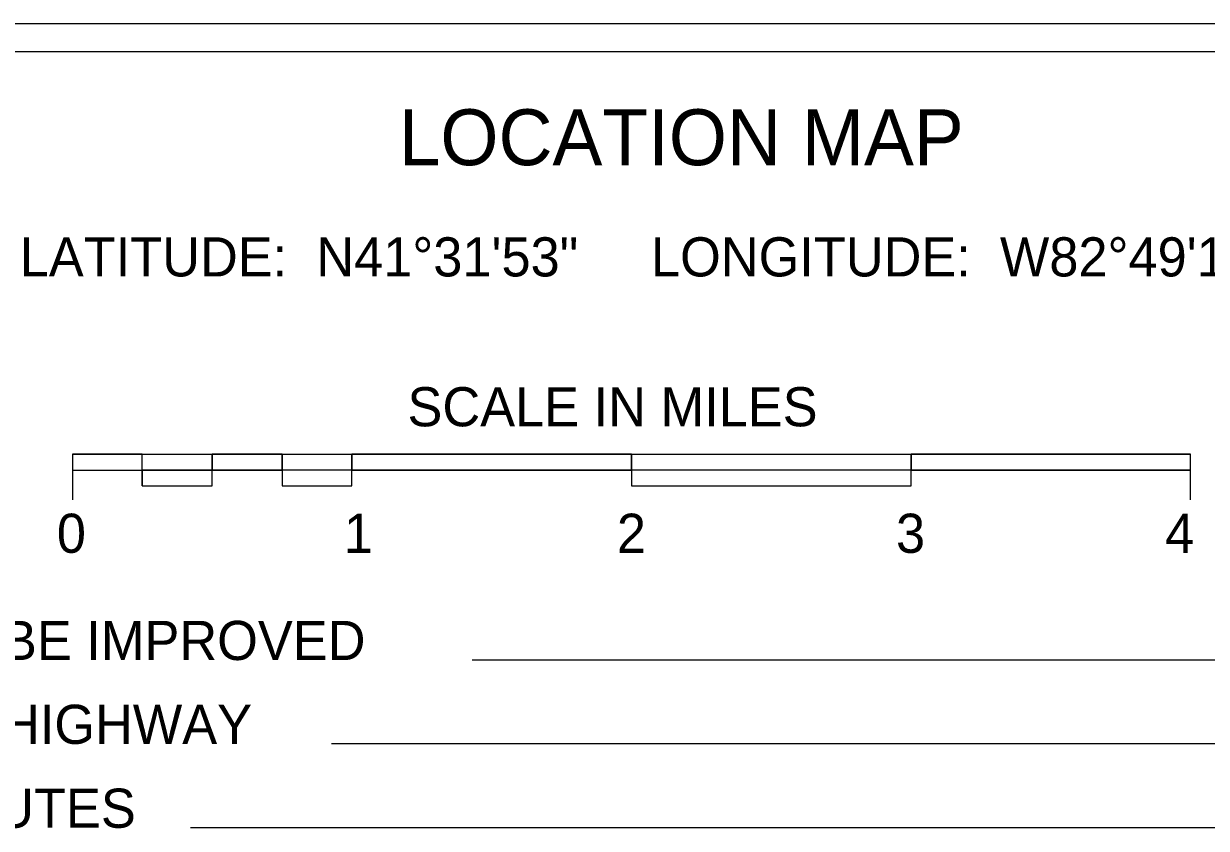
# Model space of a CAD drawing. Extents: x 63.4 to 97.4, y 0.4 to 22.4.
# Drawn here: x 66.497 to 70.728, y 11.642 to 14.52 of the extents above; entities that cross this region are included whole.
import ezdxf

# ---------------------------------------------------------------- set-up
doc = ezdxf.new("R2010")
doc.units = 0
doc.layers.add('SH_Data', color=7, linetype='Continuous')
doc.layers.add('SH_Text', color=7, linetype='Continuous')

msp = doc.modelspace()

# ---------------------------------------------------------------- linework, layer by layer
at = {"layer": 'SH_Data'}
for p, q in [((65.5123, 14.5197), (72.3123, 14.5197)), ((65.4123, 14.4197), (72.4123, 14.4197)), ((66.6718, 12.9796), (66.6718, 12.8171)), ((66.6718, 12.9796), (70.6718, 12.9796)), ((66.9218, 12.8671), (66.9218, 12.9796)), ((67.1718, 12.8671), (67.1718, 12.9796)), ((67.4218, 12.9796), (67.4218, 12.8671)), ((67.6718, 12.8671), (67.6718, 12.9796)), ((68.6718, 12.9796), (68.6718, 12.8671)), ((69.6718, 12.8671), (69.6718, 12.9796)), ((70.6718, 12.8171), (70.6718, 12.9796)), ((66.6718, 12.9233), (66.9218, 12.9233)), ((66.9218, 12.9233), (67.1718, 12.9233)), ((67.1718, 12.9233), (66.9218, 12.9233)), ((66.9218, 12.9233), (66.9218, 12.8671)), ((67.4218, 12.9233), (67.1718, 12.9233)), ((67.1718, 12.8671), (67.1718, 12.9233)), ((67.6718, 12.9233), (67.4218, 12.9233)), ((67.6718, 12.9233), (67.4218, 12.9233)), ((67.4218, 12.9233), (67.4218, 12.8671)), ((68.6718, 12.9233), (67.6718, 12.9233)), ((67.6718, 12.8671), (67.6718, 12.9233)), ((69.6718, 12.9233), (68.6718, 12.9233)), ((69.6718, 12.9233), (68.6718, 12.9233)), ((68.6718, 12.9233), (68.6718, 12.8671)), ((70.6718, 12.9233), (69.6718, 12.9233)), ((69.6718, 12.8671), (69.6718, 12.9233)), ((66.9218, 12.8671), (67.1718, 12.8671)), ((67.4218, 12.8671), (67.6718, 12.8671)), ((68.6718, 12.8671), (69.6718, 12.8671)), ((71.3083, 12.2438), (68.1023, 12.2438)), ((70.9086, 11.9438), (67.5981, 11.9438)), ((70.9086, 11.6438), (67.094, 11.6438))]:
    msp.add_line(p, q, dxfattribs=at)
for points in [[(66.6718, 12.9796), (66.6718, 12.9233), (66.9218, 12.9233), (66.9218, 12.9796)], [(67.1718, 12.9796), (67.1718, 12.9233), (67.4218, 12.9233), (67.4218, 12.9796)], [(67.6718, 12.9796), (67.6718, 12.9233), (68.6718, 12.9233), (68.6718, 12.9796)], [(70.6718, 12.9796), (69.6718, 12.9796), (69.6718, 12.9233), (70.6718, 12.9233)]]:
    msp.add_lwpolyline(points, close=True, dxfattribs=at)

# ---------------------------------------------------------------- texts
for s, p in [('SCALE IN MILES', (67.8704, 13.0796)), ('0', (66.6161, 12.6271)), ('1', (67.6427, 12.6271)), ('2', (68.6194, 12.6271)), ('3', (69.6178, 12.6271)), ('4', (70.5803, 12.6271))]:
    msp.add_text(s, height=0.14, dxfattribs=at).set_placement(p)
at = {"layer": 'SH_Text'}
for s, height, p in [('LOCATION MAP', 0.2, (67.8392, 14.0134)), ('LATITUDE:  N41°31\'53"     LONGITUDE:  W82°49\'19"', 0.14, (66.4833, 13.6156)), ('PORTION TO BE IMPROVED', 0.14, (65.203, 12.2438)), ('INTERSTATE HIGHWAY', 0.14, (65.203, 11.9438)), ('FEDERAL ROUTES', 0.14, (65.203, 11.6438))]:
    msp.add_text(s, height=height, dxfattribs=at).set_placement(p)

doc.saveas('drawing.dxf')
